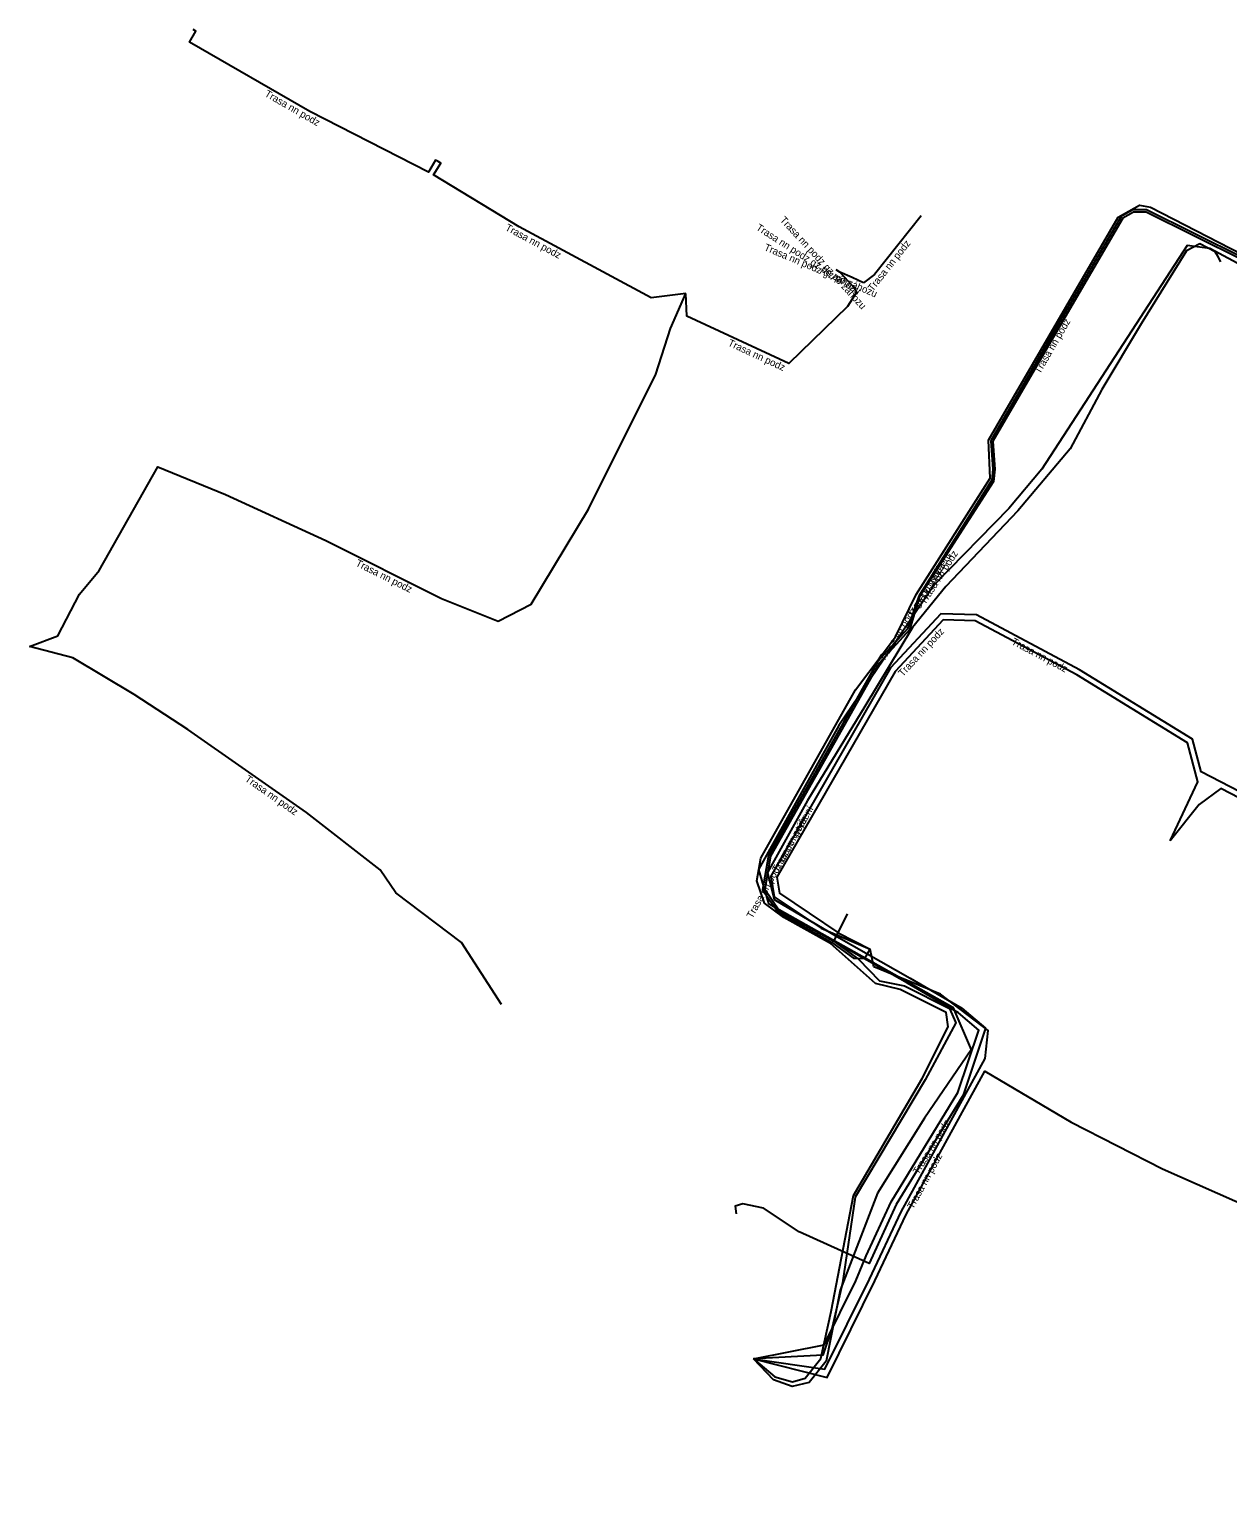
# Model space of a CAD drawing. Extents: x -528089 to -527692, y -1079306 to -1078676.
# Drawn here: x -528089 to -528006, y -1079080.7 to -1078978 of the extents above; entities that cross this region are included whole.
import ezdxf

# ---------------------------------------------------------------- set-up
doc = ezdxf.new("R2010")
doc.units = 0
for name, color, linetype in [('Popiskový text - Ostatní atributy Trasy', 7, 'Continuous'), ('Spojnice NN', 7, 'Continuous'), ('Spojnice VN', 7, 'Continuous')]:
    doc.layers.add(name, color=color, linetype=linetype)

msp = doc.modelspace()

# ---------------------------------------------------------------- linework, layer by layer
at = {"layer": 'Spojnice NN'}
for points in [[(-528060.71, -1078987.11), (-528060.89, -1078987.02), (-528061.38, -1078987.84), (-528069.6, -1078983.63), (-528077.95, -1078978.83), (-528077.51, -1078978.05), (-528077.69, -1078977.95)], [(-528043.53, -1078996.26), (-528045.94, -1078996.56), (-528055.09, -1078991.64), (-528061.03, -1078988.03), (-528060.53, -1078987.21), (-528060.71, -1078987.11)], [(-527998.19, -1078997.27), (-528011.6, -1078990.61), (-528012.47, -1078990.61), (-528013.21, -1078991.03), (-528017.57, -1078998.49), (-528022.22, -1079006.51), (-528022.08, -1079008.45), (-528022.19, -1079009.31), (-528027.31, -1079017.28), (-528028.02, -1079019.6), (-528030.12, -1079021.91), (-528037.65, -1079035.3), (-528038.04, -1079037.6), (-528037.02, -1079039.09), (-528033.31, -1079041.17), (-528031.55, -1079042.46), (-528030.08, -1079043.96), (-528028.35, -1079044.3), (-528025.23, -1079045.87), (-528024.8, -1079046.87), (-528026.93, -1079050.82), (-528031.77, -1079058.97), (-528032.65, -1079064.91), (-528033.37, -1079068), (-528034.02, -1079069.94), (-528038.84, -1079070.19)], [(-527998.15, -1078997.12), (-528011.56, -1078990.46), (-528012.51, -1078990.46), (-528013.32, -1078990.92), (-528017.7, -1078998.42), (-528022.37, -1079006.48), (-528022.23, -1079008.45), (-528022.3, -1079009.21), (-528027.37, -1079017.26), (-528028.15, -1079019.52), (-528030.24, -1079021.82), (-528037.79, -1079035.25), (-528038.2, -1079037.64), (-528037.12, -1079039.2), (-528033.4, -1079041.29), (-528031.9, -1079042.38), (-528031.1, -1079042.41), (-528030.75, -1079041.75)], [(-528027.21, -1078990.87), (-528030.43, -1078994.94), (-528031.19, -1078995.53)], [(-528006.41, -1078994.06), (-528006.62, -1078993.68), (-528006.81, -1078993.37), (-528007.87, -1078992.82), (-528008.8, -1078993.31), (-528011.93, -1078998.37), (-528014.67, -1079002.93), (-528016.87, -1079007.04), (-528020.49, -1079011.35), (-528025.48, -1079016.6), (-528027.8, -1079019.44), (-528031.12, -1079024.93), (-528035.09, -1079031.44), (-528037.86, -1079036.43), (-528037.39, -1079038.32), (-528033.06, -1079040.88), (-528027.96, -1079043.76), (-528024.39, -1079045.85), (-528022.73, -1079047.25), (-528024.28, -1079051.88), (-528028.93, -1079059.47), (-528030.81, -1079063.56), (-528035.67, -1079061.37), (-528038.14, -1079059.73), (-528039.57, -1079059.42), (-528040.1, -1079059.58), (-528040.03, -1079060.12)], [(-528006.41, -1078994.06), (-528006.62, -1078993.68), (-528006.81, -1078993.37), (-528007.87, -1078992.82), (-528008.8, -1078993.31), (-528011.93, -1078998.37), (-528014.67, -1079002.93), (-528016.87, -1079007.04), (-528020.49, -1079011.35), (-528025.48, -1079016.6), (-528027.8, -1079019.44), (-528031.12, -1079024.93), (-528035.09, -1079031.44), (-528037.86, -1079036.43), (-528037.39, -1079038.32), (-528033.06, -1079040.88), (-528027.96, -1079043.76), (-528024.39, -1079045.85), (-528022.73, -1079047.25), (-528024.28, -1079051.88), (-528028.93, -1079059.47), (-528030.81, -1079063.56), (-528035.67, -1079061.37), (-528038.14, -1079059.73), (-528039.57, -1079059.42), (-528040.1, -1079059.58), (-528040.03, -1079060.12)], [(-528032.85, -1078994.78), (-528033.1, -1078994.62)], [(-528031.19, -1078995.53), (-528031.98, -1078995.15), (-528032.85, -1078994.78)], [(-528032.85, -1078994.78), (-528031.95, -1078995.76), (-528031.66, -1078996.14)], [(-528089.05, -1079020.76), (-528087.08, -1079020.01), (-528085.59, -1079017.13), (-528084.22, -1079015.49), (-528080.16, -1079008.29), (-528075.46, -1079010.21), (-528068.49, -1079013.4), (-528060.47, -1079017.42), (-528056.55, -1079019), (-528054.25, -1079017.83), (-528050.28, -1079011.22), (-528045.6, -1079001.87), (-528044.58, -1078998.7), (-528043.53, -1078996.26)], [(-528031.66, -1078996.14), (-528032.32, -1078997.17), (-528036.39, -1079001.11), (-528043.46, -1078997.83), (-528043.53, -1078996.26)], [(-527991.56, -1079044.71), (-527992.14, -1079044.02), (-527990.29, -1079039.25), (-527999.02, -1079033.99), (-528007.77, -1079029.46), (-528008.39, -1079027.19), (-528016.21, -1079022.38), (-528023.36, -1079018.57), (-528025.83, -1079018.5), (-528029.32, -1079022.24), (-528037.64, -1079036.69), (-528037.39, -1079038.12), (-528034.13, -1079040.31), (-528030.75, -1079041.75)], [(-528009.93, -1079034.25), (-528008, -1079030.14), (-528008.73, -1079027.45), (-528016.41, -1079022.72), (-528023.46, -1079018.97), (-528025.67, -1079018.9), (-528029, -1079022.48), (-528037.22, -1079036.77), (-528037.03, -1079037.88), (-528032.91, -1079040.65), (-528030.75, -1079041.75)], [(-528056.31, -1079045.59), (-528059.09, -1079041.3), (-528063.64, -1079037.84), (-528064.73, -1079036.25), (-528069.84, -1079032.28), (-528078.07, -1079026.51), (-528081.8, -1079024.09), (-528086.05, -1079021.54), (-528089.05, -1079020.76)], [(-527971.08, -1079054.01), (-527970.55, -1079052.1), (-527972.29, -1079049.32), (-527981.3, -1079044.31), (-527989.88, -1079039.96), (-527999.22, -1079034.33), (-528006.41, -1079030.61), (-528007.91, -1079031.73), (-528009.93, -1079034.25)], [(-528038.84, -1079070.19), (-528033.94, -1079069.21), (-528031.73, -1079064.76), (-528031.01, -1079063.03), (-528029.28, -1079059.28), (-528024.65, -1079051.71), (-528023.2, -1079047.38), (-528024.62, -1079046.18), (-528028.16, -1079044.11), (-528033.26, -1079041.23), (-528032.31, -1079039.31)], [(-528038.84, -1079070.19), (-528033.89, -1079070.91), (-528030.79, -1079064.66), (-528028.59, -1079059.99), (-528022.76, -1079049.34), (-528022.56, -1079047.39), (-528025.87, -1079044.88), (-528030.48, -1079042.99), (-528030.75, -1079041.75)], [(-528038.84, -1079070.19), (-528033.71, -1079071.49), (-528030.41, -1079064.78), (-528028.23, -1079060.17), (-528022.79, -1079050.23), (-528016.8, -1079053.76), (-528010.47, -1079056.99), (-528004.25, -1079059.75), (-527995.58, -1079064.16), (-527988.26, -1079067.6), (-527975.06, -1079074.34), (-527965.76, -1079078.3), (-527957.79, -1079082.12), (-527950.56, -1079085.48), (-527943.45, -1079086.31), (-527938.1, -1079087.99), (-527929.42, -1079091.18), (-527928.68, -1079089.78), (-527927.43, -1079087.7), (-527927.38, -1079085.45)]]:
    msp.add_lwpolyline(points, dxfattribs=at)
at = {"layer": 'Spojnice VN'}
for points in [[(-528038.84, -1079070.19), (-528037.36, -1079071.43), (-528036.12, -1079071.79), (-528035.24, -1079071.53), (-528034.17, -1079070.17), (-528033.44, -1079066.89), (-528031.89, -1079058.84), (-528027.14, -1079050.74), (-528025.33, -1079047.14), (-528025.47, -1079046.15), (-528028.65, -1079044.56), (-528030.37, -1079044.13), (-528033.5, -1079041.37), (-528036.73, -1079039.57), (-528038.07, -1079038.57), (-528038.59, -1079037.02), (-528038.33, -1079035.44), (-528031.76, -1079023.76), (-528028.97, -1079020.09), (-528027.55, -1079017.15), (-528022.41, -1079009.08), (-528022.53, -1079006.45), (-528013.54, -1078990.96), (-528012.06, -1078990.14), (-528011.29, -1078990.26), (-527998.62, -1078996.79)], [(-528038.84, -1079070.19), (-528037.36, -1079071.43), (-528036.12, -1079071.79), (-528035.24, -1079071.53), (-528034.17, -1079070.17), (-528033.44, -1079066.89), (-528031.89, -1079058.84), (-528027.14, -1079050.74), (-528025.33, -1079047.14), (-528025.47, -1079046.15), (-528028.65, -1079044.56), (-528030.37, -1079044.13), (-528033.5, -1079041.37), (-528036.73, -1079039.57), (-528038.07, -1079038.57), (-528038.59, -1079037.02), (-528038.33, -1079035.44), (-528031.76, -1079023.76), (-528028.97, -1079020.09), (-528027.55, -1079017.15), (-528022.41, -1079009.08), (-528022.53, -1079006.45), (-528013.54, -1078990.96), (-528012.06, -1078990.14), (-528011.29, -1078990.26), (-527998.62, -1078996.79)], [(-528000.14, -1078996.92), (-528007.17, -1078993.13), (-528008.76, -1078992.93), (-528018.83, -1079008.44), (-528021.13, -1079011.17), (-528026.28, -1079016.45), (-528032.91, -1079026.24), (-528038.49, -1079036.23), (-528037.78, -1079038.6), (-528025, -1079045.78), (-528023.73, -1079048.75), (-528026.98, -1079053.48), (-528030.22, -1079058.69), (-528032.82, -1079065.41), (-528033.8, -1079070.34), (-528034.96, -1079071.82), (-528036.14, -1079072.11), (-528037.44, -1079071.65), (-528038.84, -1079070.19)], [(-528000.14, -1078996.92), (-528007.17, -1078993.13), (-528008.76, -1078992.93), (-528018.83, -1079008.44), (-528021.13, -1079011.17), (-528026.28, -1079016.45), (-528032.91, -1079026.24), (-528038.49, -1079036.23), (-528037.78, -1079038.6), (-528025, -1079045.78), (-528023.73, -1079048.75), (-528026.98, -1079053.48), (-528030.22, -1079058.69), (-528032.82, -1079065.41), (-528033.8, -1079070.34), (-528034.96, -1079071.82), (-528036.14, -1079072.11), (-528037.44, -1079071.65), (-528038.84, -1079070.19)]]:
    msp.add_lwpolyline(points, dxfattribs=at)

# ---------------------------------------------------------------- texts
at = {"layer": 'Popiskový text - Ostatní atributy Trasy'}
for s, rotation, p in [('Trasa nn podz', 330.0957, (-528072.79, -1078982.54)), ('Trasa nn podz', 331.7353, (-528056.1, -1078991.84)), ('Trasa nn podz gz po záhozu', 327.3808, (-528038.7, -1078991.81)), ('Trasa nn podz gz po záhozu', 312.5634, (-528037.03, -1078991.19)), ('Trasa nn podz gz po záhozu', 336.9606, (-528038.14, -1078993.24)), ('Trasa nn podz', 51.6505, (-528030.56, -1078996.15)), ('Trasa nn podz', 59.8958, (-528018.96, -1079001.88)), ('Trasa nn podz', 335.1597, (-528040.65, -1078999.86)), ('Trasa nn podz', 333.3778, (-528066.48, -1079015.13)), ('Trasa vn podz gz po vytýèení', 57.5058, (-528029.77, -1079021.84)), ('Trasa vn podz', 57.5058, (-528027.79, -1079018.74)), ('Trasa nn podz', 57.2829, (-528026.93, -1079017.89)), ('Trasa nn podz', 47.0223, (-528028.48, -1079022.88)), ('Trasa nn podz', 331.9696, (-528020.98, -1079020.57)), ('Trasa nn podz', 324.966, (-528074.15, -1079030.05)), ('Trasa nn podz gz po vytýèení', 60.9649, (-528038.91, -1079039.67)), ('Trasa nn podz', 60.9649, (-528037.13, -1079036.45)), ('Trasa nn podz', 58.5028, (-528027.39, -1079057.43)), ('Trasa nn podz', 61.318, (-528027.76, -1079059.83))]:
    msp.add_text(s, height=0.5, rotation=rotation, dxfattribs=at).set_placement(p)

doc.saveas('drawing.dxf')
